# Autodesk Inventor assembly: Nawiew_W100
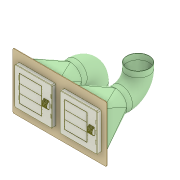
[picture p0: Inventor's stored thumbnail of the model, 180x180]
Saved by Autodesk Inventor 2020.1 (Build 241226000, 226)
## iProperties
Manager: www.cadconsulting.pl
Company: Fabian Stasiak CAD Consulting
Created: 2005-10
Part Number: Nawiew_W100
Document SubType Name: Assembly
Designer: F.Stasiak
Author: F.Stasiak
Subject: Zbiór ćwiczeń. Autodesk Inventor 2020. Kurs podstawowy
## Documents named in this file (5)
- C:\2020_Kurs_podstawowy\R6 Zespoły\Widok\Nawiew_W100.iam
- C:\2020_Kurs_podstawowy\R6 Zespoły\Widok\Płyta z otworami_W100.ipt
- C:\2020_Kurs_podstawowy\R6 Zespoły\Widok\Filtr_W100.ipt
- C:\2020_Kurs_podstawowy\R6 Zespoły\Widok\KolankoKO_W100.ipt
- C:\2020_Kurs_podstawowy\R6 Zespoły\Widok\Przesłona_W100.iam
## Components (7 placed, 4 different names)
1. Płyta z otworami_W100:1 — Wstaw:1, Wstaw:2, Wstaw:3, Wstaw:4, Wstaw:9, Wstaw:10, Wstaw:11, Wstaw:12, Wstaw:13, Wstaw:14, Wstaw:15, Wstaw:16
2. Przesłona_W100:1 [sub-assembly] — Wstaw:9, Wstaw:10
3. Przesłona_W100:2 [sub-assembly] — Wstaw:11, Wstaw:12
4. Filtr_W100:1 — Wstaw:1, Wstaw:2
5. Filtr_W100:2 — Wstaw:3, Wstaw:4
6. KolankoKO_W100:1 — Wstaw:15, Wstaw:16
7. KolankoKO_W100:2 — Wstaw:13, Wstaw:14
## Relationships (12: Insert 12)
- Wstaw:1 [Insert]: Płyta z otworami_W100:1 ↔ Filtr_W100:1
- Wstaw:2 [Insert]: Płyta z otworami_W100:1 ↔ Filtr_W100:1
- Wstaw:3 [Insert]: Płyta z otworami_W100:1 ↔ Filtr_W100:2
- Wstaw:4 [Insert]: Płyta z otworami_W100:1 ↔ Filtr_W100:2
- Wstaw:9 [Insert]: Płyta z otworami_W100:1 ↔ Przesłona_W100:1
- Wstaw:10 [Insert]: Płyta z otworami_W100:1 ↔ Przesłona_W100:1
- Wstaw:11 [Insert]: Płyta z otworami_W100:1 ↔ Przesłona_W100:2
- Wstaw:12 [Insert]: Płyta z otworami_W100:1 ↔ Przesłona_W100:2
- Wstaw:13 [Insert]: Płyta z otworami_W100:1 ↔ KolankoKO_W100:2
- Wstaw:14 [Insert]: Płyta z otworami_W100:1 ↔ KolankoKO_W100:2
- Wstaw:15 [Insert]: Płyta z otworami_W100:1 ↔ KolankoKO_W100:1
- Wstaw:16 [Insert]: Płyta z otworami_W100:1 ↔ KolankoKO_W100:1
